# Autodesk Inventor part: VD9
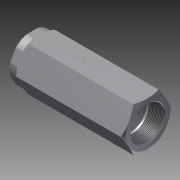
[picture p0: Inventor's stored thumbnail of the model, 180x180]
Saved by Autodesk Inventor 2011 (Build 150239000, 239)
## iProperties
Created: 2012-01
Part Number: VD9
Document SubType Name: Modeling
Designer: khramov
Density: 1 g/cm^3
Author: khramov
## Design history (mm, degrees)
derived "VD9_W1_30.ipt"
feature "Твердое тело1::VD9_W1_30.ipt" dims "d0" = 10
tag "Элемент создания маркировки1"
node "Твердое тело1"
